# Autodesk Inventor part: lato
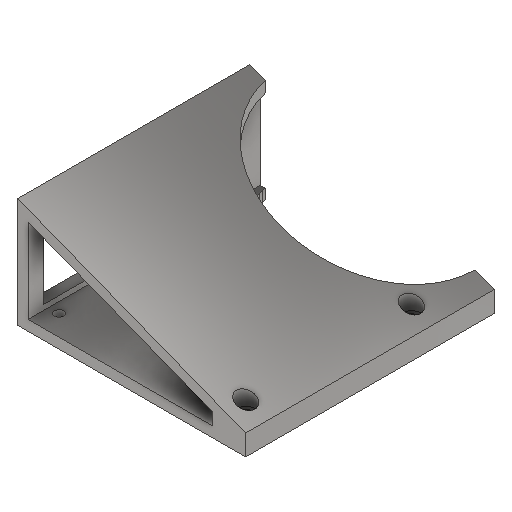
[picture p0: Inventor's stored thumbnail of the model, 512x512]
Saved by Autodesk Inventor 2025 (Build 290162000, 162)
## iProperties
Created: 2025-05
Part Number: lato
Material: Plastica PET
Document SubType Name: Modeling
Designer: R5800u
Density: 1.541 g/cm^3
Appearance: Acciaio - Lucido
Author: R5800u
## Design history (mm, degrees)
sketch "Schizzo1"
  geometry: L1 (0, 0)-(190, 0) reference; L2 (190, 0)-(190, 5) reference; L3 (0, 5)-(190, 5) reference; L4 (0, 0)-(0, 5) reference; L5 (300, -48)-(300, -53) reference; L6 (300, -48)-(300, -38); L7 (300, -38)-(190, 5); L8 (190, 5)-(190, -48); L9 (190, -48)-(300, -48); L10 (195, -2.323)-(295, -41.414); L11 (295, -41.414)-(295, -43); L12 (295, -43)-(195, -43); L13 (195, -43)-(195, -2.323); L14 (284, -37.114)-(284, -43); 1 further point
  constraints: 18 end point, 3 point on line, 2 perpendicular, 1 vertical, 3 other
  dimensions: "d0" = 10 distance of L5.start L6.end; "d1" = 5 distance between parallel lines of L7 L10; "d2" = 16 distance between parallel lines of L6 L14
extrude "Estrusione1" new body sketch "Schizzo1" distance "d3" = 120; taper "d4" = 0 deg
sketch "Schizzo2"
  geometry: L1 (0, 53)-(0, 0) reference; L2 (0, 53)-(-120, 53) reference; L3 (-120, 0)-(-120, 53) reference; L4 (0, 0)-(-120, 0) reference; L5 (-112.5, 45.5)-(-7.5, 45.5); L6 (-7.5, 45.5)-(-7.5, 7.5); L7 (-7.5, 7.5)-(-112.5, 7.5); L8 (-112.5, 7.5)-(-112.5, 45.5); L9 (-102.5, 45.5)-(-102.5, 43.336); L10 (-102.5, 43.336)-(-102.5, 7.5); 1 further point
  constraints: 12 end point, 3 point on line, 1 perpendicular, 3 other
  dimensions: "d5" = 7.5 distance between parallel lines of L2 L5; "d39" = 10 distance between parallel lines of L8 L10
extrude "Estrusione2" cut sketch "Schizzo2" stored distance "d6" = 10; taper "d7" = 0 deg
sketch "Schizzo3"
  geometry: L1 (81.5, -69.5)-(81.5, -61.5) reference; L2 (93.5, -69.5)-(81.5, -69.5) reference; L3 (93.5, -61.5)-(93.5, -69.5) reference; L4 (81.5, -61.5)-(93.5, -61.5) reference; L5 (93.5, 61.5)-(81.5, 61.5) reference; L6 (81.5, 61.5)-(81.5, 69.5) reference; L7 (81.5, 69.5)-(93.5, 69.5) reference; 1 further point
  constraints: 14 end point, 4 horizontal, 3 vertical, 8 other
extrude "Estrusione3" cut sketch "Schizzo3" distance "d8" = 10; taper "d9" = 0 deg
sketch "Schizzo4"
  geometry: L1 (0, -120)-(110, -120) reference; L2 (100, -120)-(100, 0); L3 (0, 0)-(110, 0) reference; L4 (100, -60)-(110, -60); L5 (110, 0)-(110, -120) reference; L6 (100, -10)-(10, -10); L7 (0, 0)-(0, -120) reference; 6 further points
  constraints: 6 end point, 3 point on line, 2 midpoint, 1 coincident, 1 horizontal, 1 symmetric about line, 1 vertical
  dimensions: "d11" = 10 distance from line of L4 point (100, -70); "d19" = 10 distance from line of L7 L6.end; "d34" = 10 distance between parallel lines of L5 L2; "d35" = 30 distance from line of L1 point (100, -90)
hole "Foro1" sketch "Schizzo4" at (100, -90), (100, -10), (10, -10), (10, -110) diameter "d12" = 4.5; stored, may be unused: countersink angle "d16" = 90 deg, drill point angle "d18" = 118 deg; dims "d13" = 6, "d14" = 9.4, "d15" = 2, "d17" = 20
node "Piano di lavoro1"
sketch "Schizzo6"
  geometry: C1 r 2.25 at (95, 90) reference; C2 r 2.25 at (95, 10) reference; 1 further point
hole "Foro2" sketch "Schizzo6" at (95, 10), (95, 90) diameter "d21" = 5.5; stored, may be unused: countersink angle "d25" = 90 deg, drill point angle "d27" = 118 deg; dims "d22" = 6, "d23" = 9, "d24" = 8, "d26" = 20
node "Piano di lavoro2"
sketch "Schizzo8"
  geometry: L1 (0, -148.74)-(0, -92.562); L2 (0, -148.74)-(0, -200.951); L3 (0, -205)-(0, -95) reference; L4 (-8, -102.426)-(-8, -95); L5 (-120, -95)-(0, -95) reference; A1 r 45 centre (0, -148.74) between (0.743, -103.747) and (0.743, -193.734) reference; A2 r 47 centre (0, -148.74) between (0.776, -101.747) and (0.776, -195.734); 3 further points
  constraints: 6 end point, 5 point on circle, 2 centre point, 2 point on line, 2 vertical, 4 other
  dimensions: "d36" = 2 radial gap between concentric circles of A1 A2; "d40" = 8 distance between parallel lines of L1 L4
extrude "Estrusione5" cut sketch "Schizzo8" extent not by distance; stored distance "d37" = 0; taper "d38" = 0 deg
node "Solido1"
node "Riferimento1"
node "Riferimento2"
node "Linea chiusa proiettata1"
other parameters: "d20" = 11
